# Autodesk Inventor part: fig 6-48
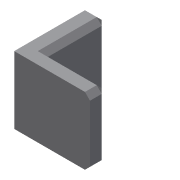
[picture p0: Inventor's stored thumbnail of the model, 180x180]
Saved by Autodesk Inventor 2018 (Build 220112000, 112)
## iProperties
Created: 2009-09
Part Number: fig 6-48
Document SubType Name: Modeling
Designer: Sham
Density: 1 g/cm^3
Material: Generic
Appearance: Default
Author: Sham
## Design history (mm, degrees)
sketch "Sketch1"
  geometry: L1 (1.789, 30)-(1.789, -5); L2 (1.789, -5)-(36.789, -5); L3 (36.789, -5)-(36.789, -15); L4 (36.789, -15)-(-8.211, -15); L5 (-8.211, -15)-(-8.211, 30); L6 (-8.211, 30)-(1.789, 30)
  constraints: 12 end point, 6 perpendicular
  dimensions: "d0" = 10 distance of L5.end L1.start; "d1" = 35 distance of L1.start L1.end; "d2" = 45 distance of L3.end L4.end; "d3" = 10 distance of L2.end L3.end (derived)
extrude "Extrusion1" new body sketch "Sketch1" distance "d4" = 40; taper "d5" = 0 deg
chamfer "Chamfer1" distance "d6" = 3; stored, may be unused: second distance "d7" = 2, angle "d8" = 45 deg
body "Solid1"
other parameters: "d1" = 35
